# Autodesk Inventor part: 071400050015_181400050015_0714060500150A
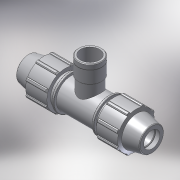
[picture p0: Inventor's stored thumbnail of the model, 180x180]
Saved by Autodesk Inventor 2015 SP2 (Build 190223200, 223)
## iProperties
Created: 2017-02
Part Number: 071400050015_181400050015_0714060500150A
Material: PVC-Piping
Description: PLASSON TEE WITH THREADED FEMALE OFFTAKE 50-1.1/2"-50
Document SubType Name: Modeling
Designer: KIM
Mass: 92.6774 g
Surface Area: 199.44 cm^2
Volume: 66.1981 cm^3
Density: 1.4 g/cm^3
Appearance: Smooth - White
Author: KIM
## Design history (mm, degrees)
derived "07140.ipt"
feature "Solid1::07140.ipt"
feature "Solid2::07140.ipt"
tag "TaggingFeature1"
body "Solid1"
other parameters: "d4" = 10.16667, "d5" = 29.28, "d7" = 96, "d11" = 4.06667, "d13" = 120 deg, "d15" = 12 deg, "d16" = 83.52, "d18" = 2.5, "d19" = 35 deg, "d20" = 17.5 deg, "d21" = 89.28, "d23" = 0, "d25" = 360 deg, "d27" = 1.92, "d33" = 1, "d42" = 43.92, "d43" = 2.88, "d46" = 1.5, "d68" = 7.32, "d72" = 76, "d76" = 44.845, "d80" = 1.34535, "d91" = 72, "d93" = 93, "d95" = 45, "d112" = 25, "d115" = 56.05625, "d116" = 135 deg, "d117" = 51.57175, "d118" = 244, "d119" = 45, "d121" = 0, "d122" = 40.5, "d124" = 0, "d128" = 0, "d129" = 5, "d130" = 7.5, "d131" = 0.3, "d132" = 0.3, "d133" = 56.05625, "E_" = 96, "A_" = 76, "l_" = 93, "l_2" = 25, "Rp_" = 44.845, "H_" = 244
